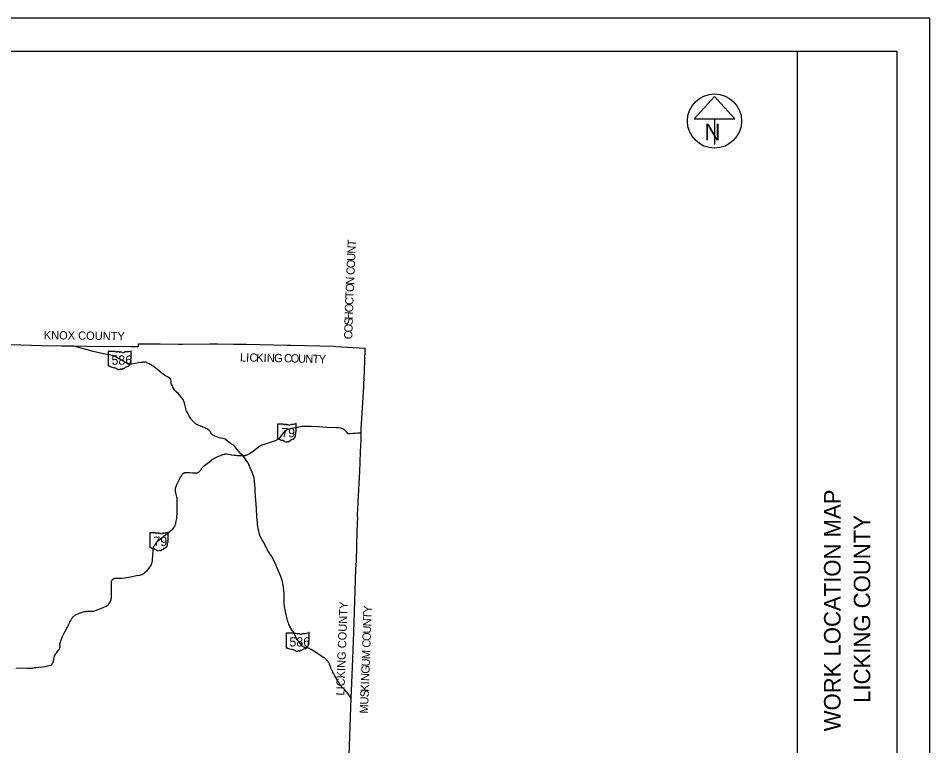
# Model space of a CAD drawing. Extents: x 1853412 to 2125412, y 78841 to 855418.
# Drawn here: x 2015090 to 2125412, y 767328 to 855418 of the extents above; entities that cross this region are included whole.
import ezdxf

# ---------------------------------------------------------------- set-up
doc = ezdxf.new("R2010")
doc.units = 0
for name, color, linetype in [('GM_X_County', 7, 'Continuous'), ('GM_X_County_Text', 7, 'Continuous'), ('GM_X_State_Location', 7, 'Continuous'), ('GM_X_State_Route', 7, 'Continuous'), ('GM_X_State_Shield', 7, 'Continuous'), ('SH_Border', 7, 'Continuous'), ('SH_Cut_Line', 7, 'Continuous'), ('SH_Data', 7, 'Continuous'), ('SH_Masking', 7, 'Continuous'), ('SH_Text', 7, 'Continuous')]:
    doc.layers.add(name, color=color, linetype=linetype)

msp = doc.modelspace()

# ---------------------------------------------------------------- linework, layer by layer
at = {"layer": 'GM_X_County'}
msp.add_lwpolyline([(2014115, 815904), (2017998, 815808), (2020382, 815768), (2021673, 815746), (2023355, 815717), (2028708, 815664), (2029367, 815674), (2029630, 815668), (2029642, 815987), (2032252, 815993), (2034492, 815973), (2034983, 815969), (2038297, 816009), (2039196, 815994), (2041129, 815964), (2042723, 815938), (2047645, 815846), (2048065, 815838), (2053316, 815692), (2053523, 815687), (2057031, 815485), (2057019, 815250), (2056899, 811568), (2056897, 811400), (2056861, 810899), (2056861, 810876), (2056863, 810840), (2056867, 810805), (2056541, 805722), (2056567, 805237), (2056538, 804363), (2056484, 802909), (2056380, 800498), (2056351, 799840), (2056130, 795281), (2056125, 795083), (2056131, 795035), (2056068, 793283), (2055973, 789772), (2055957, 789237), (2055919, 788685), (2055674, 781043), (2055513, 776843), (2055388, 773963), (2055343, 773147), (2055023, 763820)], dxfattribs=at)
at = {"layer": 'GM_X_State_Route'}
for points in [[(2029654, 813686), (2029302, 813633), (2028789, 813552), (2028645, 813551), (2028515, 813560), (2028381, 813609), (2028126, 813739), (2027312, 814168), (2026847, 814423), (2026534, 814571), (2026283, 814638), (2025407, 814794), (2024156, 815073), (2022247, 815574), (2021674, 815743)], [(2046067, 789739), (2045962, 789941), (2045911, 790035), (2045852, 790135), (2045772, 790255), (2045534, 790586), (2045403, 790755), (2045335, 790870), (2045246, 791045), (2045088, 791370), (2045024, 791509), (2044809, 791947), (2044629, 792250), (2044344, 792785), (2044203, 793304), (2044137, 793614), (2044092, 793908), (2044057, 794188), (2044031, 794403), (2043985, 795011), (2043927, 796116), (2043856, 797033), (2043783, 798155), (2043764, 798487), (2043700, 799371), (2043637, 799784), (2043413, 800466), (2043167, 801000), (2042996, 801365), (2042862, 801635), (2042599, 802028), (2042258, 802474), (2042021, 802691), (2041816, 802905), (2041692, 803051), (2041456, 803345), (2041293, 803579), (2041189, 803673), (2041048, 803761), (2040783, 803909), (2040632, 804030), (2040354, 804308), (2040267, 804394), (2040116, 804455), (2039873, 804513), (2039404, 804623), (2039204, 804675), (2039026, 804758), (2038880, 804823), (2038621, 804990), (2038489, 805117), (2038405, 805228), (2038314, 805373), (2038192, 805506), (2037995, 805646), (2037588, 805856), (2037420, 805914), (2037310, 805968), (2037219, 806010), (2037143, 806046), (2037055, 806079), (2036941, 806125), (2036843, 806162), (2036776, 806191), (2036722, 806216), (2036672, 806241), (2036631, 806265), (2036588, 806290), (2036550, 806322), (2036488, 806375), (2036459, 806404), (2036416, 806447), (2036374, 806490), (2036340, 806532), (2036268, 806599), (2036225, 806642), (2036166, 806707), (2036119, 806758), (2036077, 806810), (2036033, 806866), (2035996, 806920), (2035967, 806971), (2035831, 807189), (2035546, 807727), (2035474, 807862), (2035199, 808805), (2035071, 809238), (2034908, 809460), (2034490, 809935), (2034177, 810221), (2034031, 810349), (2033809, 810765), (2033616, 811198), (2033604, 811450), (2033562, 811659), (2033506, 811747), (2033414, 811831), (2033171, 811987), (2032809, 812211), (2032455, 812459), (2031990, 812857), (2031540, 813195), (2030955, 813563), (2030673, 813714), (2030634, 813735), (2030581, 813755), (2030522, 813772), (2030481, 813781), (2030432, 813784), (2030366, 813787), (2030311, 813783), (2030246, 813777), (2030160, 813764), (2030070, 813750), (2029959, 813734), (2029654, 813686)], [(2043160, 802748), (2043164, 802752), (2043454, 802969), (2043549, 803040), (2044314, 803625), (2044412, 803680), (2044524, 803742), (2044623, 803784), (2045008, 803904), (2045734, 804132), (2046225, 804304), (2046407, 804368), (2046537, 804434), (2046617, 804484), (2046683, 804550), (2046787, 804663), (2046872, 804772), (2047037, 804982), (2047202, 805232), (2047300, 805357), (2047452, 805484), (2047618, 805593), (2047688, 805621), (2047759, 805655), (2047929, 805709), (2048217, 805781), (2048630, 805859), (2049051, 805960), (2049195, 805984), (2049290, 805996), (2049438, 806010), (2049872, 806014), (2050540, 806010), (2051529, 805968), (2052383, 805923), (2053556, 805872), (2053908, 805854), (2054094, 805823), (2054228, 805785), (2054346, 805741), (2054479, 805665), (2054579, 805585), (2054719, 805425), (2054857, 805253), (2054942, 805160), (2054996, 805120), (2055223, 805130), (2055592, 805161), (2055927, 805188), (2056211, 805220), (2056568, 805235)], [(2031434, 791274), (2031481, 791391), (2031524, 791491), (2031618, 791652), (2031692, 791758), (2031764, 791852), (2031877, 791974), (2031981, 792090), (2032095, 792209), (2032248, 792341), (2032499, 792540), (2032787, 792772), (2033267, 793121), (2033669, 793462), (2033799, 793575), (2033893, 793674), (2033962, 793782), (2034021, 793881), (2034067, 793977), (2034104, 794100), (2034149, 794252), (2034179, 794378), (2034234, 794676), (2034266, 794847), (2034288, 794978), (2034304, 795109), (2034315, 795326), (2034321, 795678), (2034336, 796512), (2034339, 796965), (2034333, 797152), (2034328, 797223), (2034316, 797314), (2034288, 797441), (2034242, 797599), (2034202, 797776), (2034159, 797972), (2034140, 798085), (2034131, 798161), (2034126, 798263), (2034119, 798404), (2034140, 798523), (2034164, 798637), (2034193, 798738), (2034233, 798847), (2034259, 798899), (2034705, 799762), (2034764, 799873), (2034807, 799956), (2034834, 800008), (2034866, 800065), (2034913, 800142), (2034958, 800203), (2034995, 800244), (2035029, 800276), (2035060, 800303), (2035089, 800324), (2035129, 800351), (2035180, 800377), (2035218, 800393), (2035258, 800407), (2035304, 800418), (2035343, 800424), (2035387, 800428), (2035437, 800430), (2035529, 800423), (2035600, 800419), (2035691, 800412), (2035833, 800397), (2036192, 800380), (2036404, 800370), (2036648, 800370), (2036732, 800383), (2036823, 800420), (2036911, 800465), (2036973, 800508), (2037060, 800583), (2037111, 800646), (2037220, 800786), (2037322, 800938), (2037435, 801079), (2037514, 801154), (2037572, 801204), (2037742, 801346), (2038002, 801545), (2038385, 801832), (2038580, 801972), (2038719, 802066), (2038840, 802145), (2038998, 802233), (2039156, 802299), (2039325, 802375), (2039499, 802451), (2039827, 802593), (2039903, 802613), (2040054, 802640), (2040149, 802657), (2040219, 802662), (2040300, 802660), (2040521, 802627), (2040770, 802580), (2040903, 802562), (2041226, 802512), (2041406, 802495), (2041590, 802486), (2041863, 802489), (2042258, 802474), (2042359, 802480), (2042419, 802485), (2042537, 802493), (2042583, 802500), (2042635, 802511), (2042707, 802530), (2042771, 802552), (2042866, 802586), (2042968, 802631), (2043053, 802675), (2043115, 802716), (2043160, 802748)], [(2031111, 789095), (2031166, 789188), (2031202, 789252), (2031274, 789427), (2031303, 789527), (2031332, 789740), (2031350, 789909), (2031373, 790324), (2031412, 791042), (2031434, 791274)], [(2022739, 783462), (2022763, 783472), (2022937, 783529), (2023097, 783573), (2023188, 783591), (2023239, 783601), (2023366, 783610), (2023560, 783614), (2023847, 783617), (2024051, 783620), (2024168, 783630), (2024240, 783642), (2024439, 783701), (2024772, 783836), (2025099, 783956), (2025469, 784109), (2025731, 784251), (2025919, 784366), (2026006, 784438), (2026061, 784496), (2026100, 784540), (2026193, 784694), (2026247, 784789), (2026304, 784928), (2026332, 785055), (2026347, 785134), (2026360, 785239), (2026364, 785430), (2026364, 786533), (2026367, 787066), (2026370, 787127), (2026375, 787165), (2026382, 787207), (2026392, 787248), (2026402, 787291), (2026420, 787326), (2026441, 787367), (2026463, 787399), (2026481, 787431), (2026501, 787456), (2026523, 787477), (2026546, 787501), (2026576, 787524), (2026609, 787546), (2026637, 787560), (2026672, 787575), (2026707, 787586), (2026740, 787593), (2026784, 787602), (2026836, 787608), (2026946, 787611), (2027326, 787608), (2027672, 787630), (2028226, 787720), (2028885, 787829), (2029423, 787926), (2029806, 787996), (2029939, 788030), (2030036, 788064), (2030168, 788127), (2030249, 788176), (2030391, 788273), (2030494, 788369), (2030677, 788566), (2031043, 789006), (2031111, 789095)], [(2047305, 784302), (2047294, 784563), (2047287, 784832), (2047286, 785010), (2047267, 785785), (2047198, 786451), (2047128, 786989), (2047036, 787341), (2046852, 787829), (2046067, 789739)], [(2021753, 782967), (2021757, 782971), (2021814, 783023), (2021873, 783073), (2021921, 783110), (2021968, 783142), (2022035, 783182), (2022105, 783219), (2022242, 783275), (2022347, 783312), (2022521, 783372), (2022739, 783462)], [(2055344, 773144), (2055242, 773319), (2055100, 773508), (2054914, 773768), (2054781, 773913), (2054606, 774097), (2054367, 774333), (2054307, 774390), (2054191, 774512), (2054125, 774598), (2054095, 774638), (2053957, 774865), (2053814, 775097), (2053531, 775579), (2053418, 775780), (2053279, 776019), (2053181, 776198), (2053146, 776266), (2053106, 776350), (2053072, 776417), (2053051, 776469), (2052980, 776647), (2052908, 776823), (2052880, 776898), (2052774, 777194), (2052713, 777327), (2052654, 777429), (2052612, 777495), (2052577, 777546), (2052528, 777610), (2052486, 777659), (2052443, 777707), (2052404, 777745), (2052352, 777794), (2052315, 777824), (2052278, 777855), (2052221, 777896), (2052179, 777924), (2052116, 777965), (2052059, 778002), (2052006, 778033), (2051689, 778252), (2051557, 778328), (2051306, 778492), (2050532, 778979), (2050307, 779115), (2050231, 779162), (2050176, 779182), (2050112, 779198), (2049975, 779215), (2049870, 779225), (2049782, 779242), (2049714, 779254), (2049633, 779297), (2049546, 779352), (2049235, 779709), (2049073, 779905), (2048869, 780160), (2048782, 780294), (2048680, 780511), (2048569, 780766), (2048475, 780947), (2048357, 781153), (2048298, 781260), (2048059, 781642), (2047977, 781778), (2047909, 781908), (2047854, 782029), (2047827, 782094), (2047776, 782253), (2047696, 782513), (2047640, 782694), (2047534, 783200), (2047453, 783584), (2047411, 783785), (2047344, 784012), (2047328, 784105), (2047305, 784302)], [(2019302, 777412), (2019318, 777441), (2019335, 777484), (2019366, 777562), (2019375, 777628), (2019394, 777735), (2019441, 778048), (2019468, 778160), (2019491, 778233), (2019546, 778334), (2019605, 778448), (2019665, 778541), (2019744, 778640), (2019832, 778752), (2019979, 778919), (2020078, 779038), (2020134, 779176), (2020154, 779316), (2020149, 779407), (2020144, 779511), (2020140, 779597), (2020144, 779693), (2020154, 779762), (2020186, 779873), (2020234, 780015), (2020290, 780165), (2020376, 780368), (2020462, 780573), (2020532, 780737), (2020672, 781025), (2020879, 781403), (2020971, 781578), (2021072, 781778), (2021116, 781862), (2021208, 782044), (2021335, 782283), (2021397, 782403), (2021457, 782511), (2021528, 782645), (2021564, 782708), (2021592, 782754), (2021609, 782782), (2021653, 782846), (2021702, 782911), (2021753, 782967)], [(2014807, 776742), (2015208, 776755), (2016207, 776726), (2016462, 776716), (2016573, 776715), (2016688, 776707), (2016811, 776723), (2017111, 776799), (2017209, 776814), (2018334, 776942), (2018537, 776974), (2018852, 777039), (2019036, 777083), (2019088, 777104), (2019127, 777133), (2019188, 777208), (2019246, 777311), (2019302, 777412)]]:
    msp.add_lwpolyline(points, dxfattribs=at)
at = {"layer": 'GM_X_State_Shield'}
for p, q in [((2025975, 815045), (2025975, 813343)), ((2026823, 815074), (2026003, 815074)), ((2028777, 814226), (2028777, 815116)), ((2028777, 814226), (2028777, 814226)), ((2046483, 806257), (2046483, 804556)), ((2047161, 806286), (2046505, 806286)), ((2048724, 805439), (2048724, 806329)), ((2048724, 805439), (2048724, 805439)), ((2031007, 793091), (2031007, 791390)), ((2031685, 793121), (2031029, 793121)), ((2033248, 792273), (2033248, 793163)), ((2033248, 792273), (2033248, 792273)), ((2047511, 780930), (2047511, 779229)), ((2048359, 780959), (2047539, 780959)), ((2050313, 780111), (2050313, 781001)), ((2050313, 780112), (2050313, 780111))]:
    msp.add_line(p, q, dxfattribs=at)
for centre, radius, start, end in [((2046509, 806261), 26, 98.1301, 188.1301), ((2047318, 806484), 252, 231.61951, 271.11188), ((2047401, 805331), 904, 80.48669, 94.98827), ((2047607, 806270), 72.7, 219.79206, 297.10237), ((2047713, 806073), 151, 54.46668, 119.14113), ((2047908, 806343), 182, 233.85621, 294.82819), ((2048229, 805767), 478, 97.34618, 120.76885), ((2047926, 808606), 2377, 275.84447, 288.90645), ((2048719, 805373), 38.6, 107.94398, 210.33697), ((2048473, 805261), 232, 340.03296, 23.64957), ((2048700, 806332), 25, 351.86209, 97.738), ((2048698, 805435), 26.7, 289.60381, 7.73413), ((2046509, 804552), 26.2, 171.95839, 258.30661), ((2046513, 804726), 200, 267.33899, 280.60386), ((2046554, 804458), 72.1, 29.74838, 93.27175), ((2047464, 805986), 1716, 240.41292, 257.1985), ((2046952, 803792), 537, 47.18416, 75.83597), ((2047897, 804391), 192, 282.87319, 323.27711), ((2048310, 804078), 326, 94.40312, 142.57675), ((2048059, 804953), 595, 292.30889, 8.98584), ((2048814, 805066), 169, 136.8065, 186.92959), ((2047533, 804449), 341, 230.70037, 286.29184), ((2047730, 803861), 280, 85.69512, 111.20995), ((2047755, 804322), 182, 268.77702, 315.54927), ((2047919, 804157), 51.1, 65.75173, 132.64842), ((2031033, 793095), 26, 98.1301, 188.1301), ((2031842, 793318), 252, 231.61951, 271.11188), ((2031925, 792166), 904, 80.48669, 94.98827), ((2032130, 793104), 72.7, 219.79206, 297.10237), ((2032237, 792907), 151, 54.46668, 119.14113), ((2032432, 793177), 182, 233.85621, 294.82819), ((2032753, 792601), 478, 97.34618, 120.76885), ((2032450, 795440), 2377, 275.84447, 288.90645), ((2033242, 792208), 38.6, 107.94398, 210.33697), ((2032997, 792095), 232, 340.03296, 23.64957), ((2033223, 793167), 25, 351.86209, 97.738), ((2033222, 792270), 26.7, 289.60381, 7.73413), ((2031033, 791387), 26.2, 171.95839, 258.30661), ((2031037, 791561), 200, 267.33899, 280.60386), ((2031078, 791292), 72.1, 29.74838, 93.27175), ((2031988, 792821), 1716, 240.41292, 257.1985), ((2031476, 790626), 537, 47.18416, 75.83597), ((2032057, 791284), 341, 230.70037, 286.29184), ((2032279, 791156), 182, 268.77702, 315.54927), ((2032443, 790992), 51.1, 65.75173, 132.64842), ((2032421, 791225), 192, 282.87319, 323.27711), ((2032834, 790913), 326, 94.40312, 142.57675), ((2032583, 791787), 595, 292.30889, 8.98584), ((2033338, 791901), 169, 136.8065, 186.92959), ((2032254, 790696), 280, 85.69512, 111.20995)]:
    msp.add_arc(centre, radius, start, end, dxfattribs=at)
for centre, major_axis, start_param, end_param in [((2026007, 815048), (32.5, 0), 1.7126934, 3.2834897), ((2027019, 815271), (315, 0), 4.042523, 4.731795), ((2027123, 814119), (1130, 0), 1.4047578, 1.6578581), ((2027380, 815057), (90.8, 0), 3.8360951, 5.1854146), ((2027513, 814860), (189, 0), 0.950623, 2.079405), ((2027757, 815130), (227, 0), 4.0815608, 5.1457227), ((2028158, 814554), (598, 0), 1.6990114, 2.1078141), ((2027779, 817393), (2971, 0), 4.8143942, 5.0423688), ((2028770, 814161), (48.3, 0), 1.8839779, 3.6710726), ((2028746, 815120), (31.2, 0), 6.1411519, 7.9890352), ((2028744, 814223), (33.4, 0), 5.05454, 6.4181714), ((2026008, 813340), (32.7, 0), 3.00124, 4.5083009), ((2026013, 813514), (250, 0), 4.6659457, 4.8974612), ((2026064, 813245), (90.1, 0), 0.5192072, 1.6278991), ((2027201, 814774), (2146, 0), 4.1959971, 4.4889607), ((2026562, 812579), (671, 0), 0.8235189, 1.3235874), ((2028259, 812866), (407, 0), 1.6476453, 2.4884337), ((2027945, 813740), (743, 0), 5.1017525, 6.4400178), ((2028889, 813854), (211, 0), 2.3877238, 3.2625369), ((2028463, 814048), (290, 0), 5.9346948, 6.6959481), ((2027288, 813237), (426, 0), 4.0264811, 4.9967352), ((2027534, 812649), (350, 0), 1.495662, 1.9409797), ((2027565, 813109), (227, 0), 4.6910439, 5.5073738), ((2027770, 812945), (63.9, 0), 1.1475842, 2.3151517), ((2027743, 813178), (240, 0), 4.9370686, 5.64225), ((2047543, 780934), (32.5, 0), 1.7126934, 3.2834897), ((2048555, 781157), (315, 0), 4.042523, 4.731795), ((2048659, 780004), (1130, 0), 1.4047578, 1.6578581), ((2048916, 780942), (90.8, 0), 3.8360951, 5.1854146), ((2049049, 780746), (189, 0), 0.950623, 2.079405), ((2049293, 781015), (227, 0), 4.0815608, 5.1457227), ((2049694, 780440), (598, 0), 1.6990114, 2.1078141), ((2049315, 783278), (2971, 0), 4.8143942, 5.0423688), ((2050306, 780046), (48.3, 0), 1.8839779, 3.6710726), ((2049999, 779934), (290, 0), 5.9346948, 6.6959481), ((2050282, 781005), (31.2, 0), 6.1411519, 7.9890352), ((2050280, 780108), (33.4, 0), 5.05454, 6.4181714), ((2047544, 779225), (32.7, 0), 3.00124, 4.5083009), ((2047549, 779399), (250, 0), 4.6659457, 4.8974612), ((2047600, 779131), (90.1, 0), 0.5192072, 1.6278991), ((2048737, 780659), (2146, 0), 4.1959971, 4.4889607), ((2048098, 778464), (671, 0), 0.8235189, 1.3235874), ((2049306, 778830), (63.9, 0), 1.1475842, 2.3151517), ((2049279, 779064), (240, 0), 4.9370686, 5.64225), ((2049795, 778751), (407, 0), 1.6476453, 2.4884337), ((2049481, 779626), (743, 0), 5.1017525, 6.4400178), ((2050425, 779739), (211, 0), 2.3877238, 3.2625369), ((2048824, 779122), (426, 0), 4.0264811, 4.9967352), ((2049070, 778534), (350, 0), 1.495662, 1.9409797), ((2049101, 778995), (227, 0), 4.6910439, 5.5073738)]:
    msp.add_ellipse(centre, major_axis=major_axis, ratio=0.8, start_param=start_param, end_param=end_param, dxfattribs=at)
at = {"layer": 'SH_Border'}
msp.add_line((2109412, 683418), (2109412, 851418), dxfattribs=at)
msp.add_lwpolyline([(1865412, 851418), (2121412, 851418), (2121412, 683418), (1865412, 683418)], close=True, dxfattribs=at)
at = {"layer": 'SH_Cut_Line'}
msp.add_lwpolyline([(1853412, 679418), (2125412, 679418), (2125412, 855418), (1853412, 855418)], close=True, dxfattribs=at)
at = {"layer": 'SH_Masking'}
msp.add_circle((2099358, 842966), 3280, dxfattribs=at)
at = {"layer": 'SH_Text'}
for p, q in [((2099358, 845956), (2096897, 843226)), ((2101819, 843226), (2099358, 845956)), ((2096897, 843226), (2101819, 843226)), ((2099358, 843226), (2099358, 840132))]:
    msp.add_line(p, q, dxfattribs=at)
msp.add_circle((2099358, 842966), 3280, dxfattribs=at)

# ---------------------------------------------------------------- texts
at = {"layer": 'GM_X_County_Text'}
for s, rotation, p in [('T', 87.57747, (2055938, 827783)), ('N', 87.57765, (2055900, 826900)), ('U', 87.57765, (2055863, 826016)), ('C', 87.57735, (2055791, 824319)), ('O', 87.57821, (2055826, 825133)), ('O', 87.58091, (2055704, 822249)), ('N', 87.57873, (2055741, 823132)), ('T', 87.61951, (2055673, 821502)), ('O', 87.99332, (2055610, 819806)), ('C', 87.73455, (2055641, 820689)), ('H', 88.14677, (2055581, 818923)), ('S', 88.4429, (2055563, 818247)), ('KNOX COUNTY', 359.20933, (2018174, 816558)), ('O', 88.62214, (2055541, 817364)), ('C', 88.70029, (2055523, 816550)), ('L', 359.04675, (2041917, 813862)), ('I', 358.96503, (2042663, 813850)), ('C', 358.94354, (2043070, 813842)), ('K', 358.92618, (2043885, 813827)), ('I', 358.92369, (2044767, 813811)), ('N', 358.92127, (2045174, 813803)), ('G', 358.88587, (2046057, 813787)), ('C', 358.71051, (2047244, 813763)), ('O', 358.60959, (2048058, 813745)), ('U', 358.47227, (2048940, 813723)), ('N', 358.42486, (2049822, 813700)), ('T', 358.41862, (2050705, 813676)), ('Y', 358.41862, (2051451, 813655)), ('LICKING COUNTY', 87.88958, (2054551, 773397)), ('T', 88.08728, (2057831, 782654)), ('Y', 88.08728, (2057855, 783401)), ('N', 88.07142, (2057801, 781772)), ('U', 88.04108, (2057771, 780889)), ('C', 87.95372, (2057711, 779191)), ('O', 88.00104, (2057740, 780006)), ('U', 87.89071, (2057628, 776916)), ('M', 87.93812, (2057661, 777799)), ('G', 87.84997, (2057595, 776033)), ('N', 87.82043, (2057561, 775151)), ('K', 87.79974, (2057512, 773862)), ('I', 87.80695, (2057546, 774744)), ('S', 87.79761, (2057486, 773182)), ('M', 87.7975, (2057410, 771214)), ('U', 87.79749, (2057452, 772300))]:
    msp.add_text(s, height=1000, rotation=rotation, dxfattribs=at).set_placement(p)
at = {"layer": 'GM_X_State_Location'}
for s, p in [('586', (2026878, 813991)), ('79', (2047259, 805230)), ('586', (2040553, 803800)), ('79', (2031845, 792017)), ('586', (2048689, 779860)), ('79', (2015403, 776551))]:
    msp.add_text(s, height=1, rotation=0.00001, dxfattribs=at).set_placement(p)
for s, p in [('s', (2027231, 814063)), ('r', (2027231, 814063)), ('s', (2047510, 805303)), ('r', (2047510, 805303)), ('s', (2040906, 803873)), ('r', (2040906, 803873)), ('s', (2032097, 792090)), ('r', (2032097, 792090)), ('s', (2049042, 779933)), ('r', (2049042, 779933)), ('s', (2015654, 776624)), ('r', (2015654, 776624))]:
    msp.add_text(s, height=1, dxfattribs=at).set_placement(p)
at = {"layer": 'GM_X_State_Shield'}
for s, p in [('586', (2026378, 813463)), ('79', (2046930, 804676)), ('79', (2031454, 791510)), ('586', (2047914, 779349))]:
    msp.add_text(s, height=1120.7, dxfattribs=at).set_placement(p)
at = {"layer": 'SH_Data'}
for s, p in [('WORK LOCATION MAP', (2114612, 769077)), ('LICKING COUNTY', (2118212, 772526))]:
    msp.add_text(s, height=2000, rotation=90, dxfattribs=at).set_placement(p)
at = {"layer": 'SH_Text'}
msp.add_text('N', height=2000, dxfattribs=at).set_placement((2098148, 840635))

doc.saveas('drawing.dxf')
